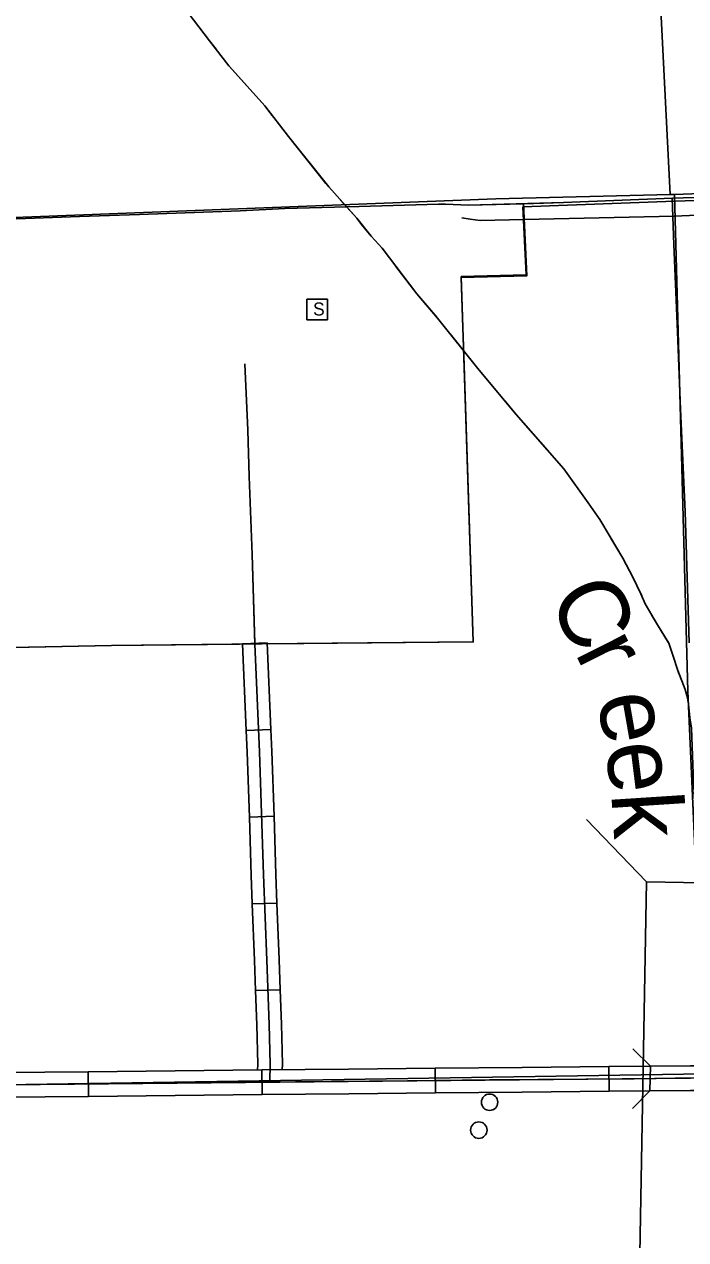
# Model space of a CAD drawing. Extents: x 646058 to 725608, y 1473014 to 1561048.
# Drawn here: x 653486 to 655499, y 1544485 to 1548182 of the extents above; entities that cross this region are included whole.
import ezdxf

# ---------------------------------------------------------------- set-up
doc = ezdxf.new("R2010")
doc.units = 0
doc.layers.add('Default', color=7, linetype='Continuous')

msp = doc.modelspace()

# ---------------------------------------------------------------- linework, layer by layer
at = {"layer": 'Default'}
for p, q in [((654346.1, 1547346.3), (654408.6, 1547346.3)), ((654346.1, 1547283.8), (654346.1, 1547346.3)), ((654408.6, 1547283.8), (654408.6, 1547346.3)), ((654346.1, 1547283.8), (654408.6, 1547283.8)), ((654149.8, 1546297.9), (654224.7, 1546301.2)), ((654161.4, 1546034.2), (654236.3, 1546037.5)), ((654170.9, 1545770.8), (654245.8, 1545773.2)), ((655379.4, 1545573.8), (655196.3, 1545763.9)), ((654179.8, 1545506.8), (654254.8, 1545509.5)), ((654189.4, 1545243), (654264.3, 1545245.7)), ((654736.7, 1545006.9), (654737.4, 1544932)), ((655265.4, 1544937.2), (655264.7, 1545012.2)), ((655391.1, 1545013.5), (655389.7, 1544938.5)), ((653680.7, 1544996.4), (653681.5, 1544921.4)), ((654209.5, 1544926.7), (654208.7, 1545001.7))]:
    msp.add_line(p, q, dxfattribs=at)
for points in [[(655451.2, 1547664.5), (655405.7, 1548566.9), (655377.8, 1550308.6)], [(653948.8, 1548263.2), (653968.2, 1548238.7), (654049.9, 1548131.6), (654069.5, 1548106.3)], [(653968.2, 1548238.7), (654049.9, 1548131.6), (654108.2, 1548056.4), (654217.8, 1547934.6), (654289.9, 1547840.6), (654412.2, 1547687.8), (654497.4, 1547592.8), (654541.1, 1547538), (654574.6, 1547501.4), (654680.1, 1547362.8), (654743.6, 1547288.7), (654869.9, 1547130.8), (654982.6, 1546995.7), (655127.7, 1546830.2), (655202.3, 1546726.6), (655237.3, 1546676.4), (655268.8, 1546623), (655307.3, 1546558.1), (655337.3, 1546500.2), (655362.2, 1546450.4), (655374.8, 1546419.9), (655412.9, 1546356), (655446.9, 1546299.6), (655459.6, 1546263.1), (655474.3, 1546216.3), (655496.6, 1546159)], [(653968.2, 1548238.7), (654049.9, 1548131.6), (654108.2, 1548056.4), (654217.8, 1547934.6), (654289.9, 1547840.6), (654412.2, 1547687.8), (654497.4, 1547592.8), (654541.1, 1547538), (654574.6, 1547501.4), (654680.1, 1547362.8), (654743.6, 1547288.7), (654869.9, 1547130.8), (654982.6, 1546995.7), (655127.7, 1546830.2), (655202.3, 1546726.6), (655237.3, 1546676.4), (655268.8, 1546623), (655307.3, 1546558.1), (655337.3, 1546500.2), (655362.2, 1546450.4), (655374.8, 1546419.9), (655412.9, 1546356), (655446.9, 1546299.6), (655459.6, 1546263.1), (655474.3, 1546216.3), (655496.6, 1546159)], [(654110.2, 1548054.3), (654217.8, 1547934.6), (654240.3, 1547905.2)], [(654280.5, 1547852.8), (654289.9, 1547840.6), (654404, 1547698.1)], [(649175.8, 1547448.5), (650142.8, 1547491.6), (652791.8, 1547568.9), (652828.4, 1547570), (654920.6, 1547651.9), (655451.2, 1547664.5), (655464.9, 1547665), (658000, 1547762.6)], [(656094.5, 1547678.8), (656029.2, 1547676.6), (655893.5, 1547671), (655593.3, 1547657.8), (655458.5, 1547653.3), (655127, 1547640.1), (654837.5, 1547632), (654767.5, 1547635.7), (654746.2, 1547635.7), (654504.5, 1547628.3), (654278.4, 1547621.7), (654142.8, 1547615), (653836.4, 1547604), (653654.4, 1547597.3), (653295.7, 1547584.1), (652792.5, 1547570.8)], [(655003.3, 1547627.3), (655465.5, 1547644.7), (656425.6, 1547675.7)], [(656279.8, 1547696.4), (656260.9, 1547682.1), (656249.3, 1547677.7), (656228, 1547675.5), (656187.8, 1547677.7), (656131.3, 1547680.1), (656029.2, 1547676.6), (655893.5, 1547671), (655593.3, 1547657.8), (655458.5, 1547653.3), (655127, 1547640.1), (655005.4, 1547636.7)], [(655006.1, 1547636.7), (654837.5, 1547632), (654767.5, 1547635.7), (654746.2, 1547635.7), (654504.5, 1547628.3), (654278.4, 1547621.7), (654142.8, 1547615), (653836.4, 1547604), (653654.4, 1547597.3), (653295.7, 1547584.1), (652792.5, 1547570.8)], [(654447.5, 1547648.5), (654497.4, 1547592.8), (654512.5, 1547573.9)], [(654815.8, 1547411.7), (655015.4, 1547417.4), (655005.4, 1547636.7)], [(655509.6, 1546301.3), (655496.8, 1546700.7), (655483.2, 1547012), (655473.3, 1547247.4), (655462.4, 1547512.5), (655457, 1547653.3)], [(655556.4, 1544989.8), (655505.1, 1546154.1), (655464.9, 1547665)], [(655465, 1547598.8), (656190.2, 1547631.1), (656206.5, 1547629.1), (656229.1, 1547620.4), (656261.7, 1547613.4), (656310.4, 1547644.6)], [(654815.7, 1547415), (655012.7, 1547420.7), (655003.3, 1547627.3)], [(654817.4, 1547593.7), (654843.1, 1547589.9), (654872.9, 1547585.5), (655007.4, 1547588.5), (655463.9, 1547598.7)], [(654512.5, 1547573.9), (654541.1, 1547538), (654574.6, 1547501.4), (654576.7, 1547498.6)], [(654616.7, 1547446.1), (654680.1, 1547362.8), (654740.8, 1547291.9)], [(653194.3, 1546281.9), (653750.9, 1546292.4), (654208.4, 1546297.4), (654852.1, 1546303.6), (654815.7, 1547415)], [(654233.5, 1546297.6), (654852.1, 1546303.6), (654840.8, 1546647.9), (654823.5, 1547174.5), (654820.8, 1547258.9), (654815.8, 1547411.7)], [(654782.2, 1547240.5), (654869.9, 1547130.8), (654906.8, 1547086.6)], [(654187.3, 1546297.1), (654179.1, 1546569.7), (654169.9, 1546806.9), (654165.7, 1546948.2), (654157.5, 1547149.4)], [(654187.2, 1546299.6), (654179.1, 1546569.7), (654169.9, 1546806.9), (654165.7, 1546948.2), (654157.5, 1547149.4)], [(654949.1, 1547035.9), (654982.6, 1546995.7), (655078.6, 1546886.2)], [(655122.1, 1546836.6), (655127.7, 1546830.2), (655202.3, 1546726.6), (655237.3, 1546676.4), (655237.6, 1546675.8)], [(655271.2, 1546619), (655307.3, 1546558.1), (655337.3, 1546500.2), (655362.2, 1546450.4), (655364.6, 1546444.5)], [(655395, 1546386.1), (655412.9, 1546356), (655445.9, 1546301.2)], [(654224.7, 1546301.2), (654236.3, 1546037.5)], [(655445.9, 1546301.2), (655446.9, 1546299.6), (655459.6, 1546263.1), (655474.3, 1546216.3), (655477.7, 1546207.6)], [(651561.1, 1546237.7), (652190.3, 1546266.3), (652616, 1546274.9), (652849.2, 1546279.6), (653194.3, 1546281.9), (653551.4, 1546288.6), (653750.9, 1546292.4), (654140.3, 1546296.6)], [(654149.8, 1546297.9), (654161.4, 1546034.2)], [(654187.3, 1546297.1), (654201.8, 1545969.3), (654214.2, 1545594.9), (654223.5, 1545336), (654230.7, 1545140), (654233.8, 1545019.3), (654232.8, 1544967.7)], [(655496.6, 1546159), (655503.7, 1546134.1), (655506.8, 1546114.8), (655510.8, 1546072.7), (655516.4, 1546041.2), (655517.9, 1545985.3), (655521.5, 1545903.1), (655522, 1545876.7), (655526.6, 1545819.8), (655524.5, 1545754.8), (655530.6, 1545700.5), (655535.2, 1545631.4), (655539.8, 1545567.4), (655540.3, 1545524.8), (655540.8, 1545432.4), (655549.9, 1545247.1), (655551.4, 1545169.9), (655558.5, 1545039.9), (655558.6, 1545037.9)], [(655496.6, 1546159), (655503.7, 1546134.1), (655506.8, 1546114.8), (655510.8, 1546072.7), (655516.4, 1546041.2), (655517.9, 1545985.3), (655521.5, 1545903.1), (655522, 1545876.7), (655526.6, 1545819.8), (655524.5, 1545754.8), (655530.6, 1545700.5), (655535.2, 1545631.4), (655539.8, 1545567.4), (655540.3, 1545524.8), (655540.8, 1545432.4), (655549.9, 1545247.1), (655551.4, 1545169.9), (655558.5, 1545039.9), (655563.1, 1544925.1), (655564.6, 1544856.1), (655574.3, 1544610.9), (655580.4, 1544512.4), (655585.4, 1544345.8)], [(654161.4, 1546034.2), (654164.3, 1545967.9), (654170.9, 1545770.8)], [(654236.3, 1546037.5), (654239.3, 1545970.8), (654245.8, 1545773.2)], [(654170.9, 1545770.8), (654176.7, 1545593.6), (654179.8, 1545506.8)], [(654245.8, 1545773.2), (654251.7, 1545596.2), (654254.8, 1545509.5)], [(654179.8, 1545506.8), (654186, 1545334.6), (654189.4, 1545243)], [(654254.8, 1545509.5), (654261, 1545337.3), (654264.3, 1545245.7)], [(654189.4, 1545243), (654193.2, 1545138.8), (654196.3, 1545019.2), (654195.9, 1545001.5)], [(654264.3, 1545245.7), (654268.2, 1545141.1), (654271.3, 1545019.4), (654271, 1545002.3)], [(655337.6, 1545066), (655391.1, 1545013.5)], [(654736.7, 1545006.9), (654472.7, 1545004.3)], [(655000.7, 1545009.6), (654736.7, 1545006.9)], [(655264.7, 1545012.2), (655000.7, 1545009.6)], [(655529.7, 1545014.4), (655513.4, 1545014.7), (655264.7, 1545012.2)], [(655513.3, 1544977.2), (652908.5, 1544951.1), (652283.8, 1544936.9), (652264, 1544932.5), (652246.2, 1544927.7), (652221.6, 1544930.1), (651569.2, 1544908.6)], [(652899, 1544951.5), (653207, 1544956), (653532.5, 1544957.6), (653765.9, 1544960.1), (653984.3, 1544963.4), (654201.9, 1544964.3), (654420.3, 1544966.8), (654652, 1544968.4), (654901.9, 1544971.8), (655342.1, 1544975.1), (655590.4, 1544979.2)], [(652908.6, 1544947.9), (655556.4, 1544989.8)], [(653680.7, 1544996.4), (653416.7, 1544993.7)], [(653944.7, 1544999), (653680.7, 1544996.4)], [(654208.7, 1545001.7), (653944.7, 1544999)], [(654472.7, 1545004.3), (654208.7, 1545001.7)], [(654737.4, 1544932), (654473.4, 1544929.3)], [(654737.4, 1544932), (655001.4, 1544934.6)], [(655001.4, 1544934.6), (655265.4, 1544937.2)], [(655528.3, 1544939.4), (655513.1, 1544939.7), (655265.4, 1544937.2)], [(655389.7, 1544938.5), (655337.2, 1544884.9)], [(653681.5, 1544921.4), (653417.5, 1544918.7)], [(653681.5, 1544921.4), (653945.5, 1544924)], [(653945.5, 1544924), (654209.5, 1544926.7)], [(654473.4, 1544929.3), (654209.5, 1544926.7)]]:
    msp.add_lwpolyline(points, dxfattribs=at)
msp.add_lwpolyline([(655753.5, 1544378.7), (655775.4, 1545566.5), (655379.4, 1545573.8), (655357.5, 1544386)], close=True, dxfattribs=at)
for centre in [(654901.8, 1544903.6), (654869.1, 1544818.7)]:
    msp.add_circle(centre, 25, dxfattribs=at)

# ---------------------------------------------------------------- texts
msp.add_text('S', height=39.6, dxfattribs=at).set_placement((654364.7, 1547296.6))
for s, rotation, p in [('C', 295.9274, (655078.2, 1546439.7)), ('r', 296.7187, (655159.7, 1546272)), ('e', 279.9219, (655227.9, 1546136.5)), ('e', 277.1444, (655253.4, 1545990.4)), ('k', 273.7151, (655272, 1545842.7))]:
    msp.add_text(s, height=211.2, rotation=rotation, dxfattribs=at).set_placement(p)

doc.saveas('drawing.dxf')
